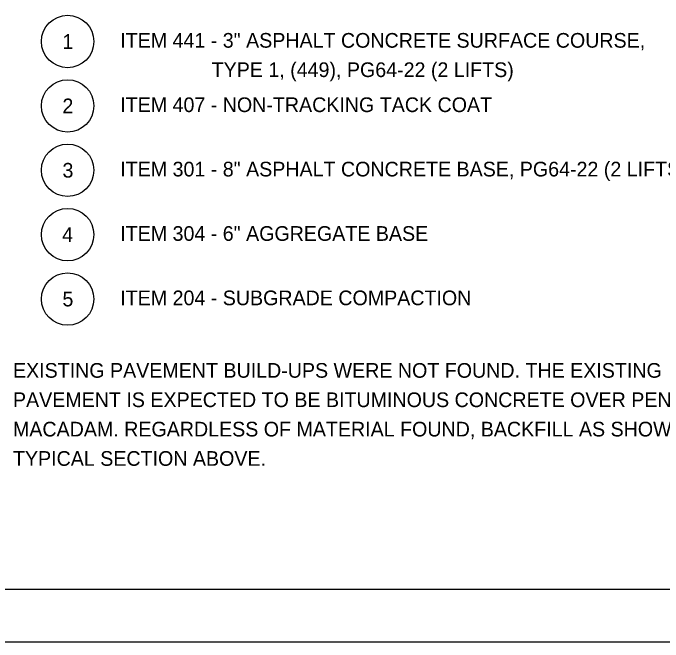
# Model space of a CAD drawing. Extents: x 0 to 34, y 0 to 22.
# Drawn here: x 24.66 to 30.86, y 0 to 6 of the extents above; entities that cross this region are included whole.
import ezdxf

# ---------------------------------------------------------------- set-up
doc = ezdxf.new("R2010")
doc.units = 0
for name, color, linetype in [('SH_Border', 7, 'Continuous'), ('SH_Cut_Line', 7, 'Continuous'), ('SH_Text', 7, 'Continuous')]:
    doc.layers.add(name, color=color, linetype=linetype)

msp = doc.modelspace()

# ---------------------------------------------------------------- linework, layer by layer
at = {"layer": 'SH_Border'}
msp.add_lwpolyline([(1.5, 21.5), (33.5, 21.5), (33.5, 0.5), (1.5, 0.5)], close=True, dxfattribs=at)
at = {"layer": 'SH_Cut_Line'}
msp.add_lwpolyline([(0, 0), (34, 0), (34, 22), (0, 22)], close=True, dxfattribs=at)
at = {"layer": 'SH_Text'}
for centre in [(25.1816, 5.7265), (25.1816, 5.1125), (25.1816, 4.4985), (25.1816, 3.8845), (25.1816, 3.2706)]:
    msp.add_circle(centre, 0.25, dxfattribs=at)

# ---------------------------------------------------------------- texts
for s, p in [('1', (25.1317, 5.6565)), ('ITEM 441 - 3" ASPHALT CONCRETE SURFACE COURSE, ', (25.6832, 5.6674)), ('      TYPE 1, (449), PG64-22 (2 LIFTS)', (26.2432, 5.3874)), ('2', (25.1318, 5.0425)), ('ITEM 407 - NON-TRACKING TACK COAT ', (25.6832, 5.0535)), ('3', (25.1324, 4.4285)), ('ITEM 301 - 8" ASPHALT CONCRETE BASE, PG64-22 (2 LIFTS)', (25.6832, 4.4395)), ('4', (25.1288, 3.8145)), ('ITEM 304 - 6" AGGREGATE BASE', (25.6832, 3.8255)), ('ITEM 204 - SUBGRADE COMPACTION', (25.6832, 3.2116)), ('5', (25.1321, 3.2006))]:
    msp.add_text(s, height=0.14, rotation=360, dxfattribs=at).set_placement(p)
for s, p in [('EXISTING PAVEMENT BUILD-UPS WERE NOT FOUND. THE EXISTING ', (24.66, 2.52)), ('PAVEMENT IS EXPECTED TO BE BITUMINOUS CONCRETE OVER PENETRATION ', (24.66, 2.24)), ('MACADAM. REGARDLESS OF MATERIAL FOUND, BACKFILL AS SHOWN IN ', (24.66, 1.96)), ('TYPICAL SECTION ABOVE.', (24.66, 1.68))]:
    msp.add_text(s, height=0.14, dxfattribs=at).set_placement(p)

doc.saveas('drawing.dxf')
